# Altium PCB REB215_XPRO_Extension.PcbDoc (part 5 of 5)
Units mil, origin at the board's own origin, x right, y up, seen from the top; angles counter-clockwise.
Board outline 4055.74 x 2606 mil, 6 copper layers (Top Layer LF-signals, Signal Layer 1, Internal Plane 1, Mid-1, Mid-2, Bottom Layer LF-signals), stack 58.434 mil thick; 278 components, 292 nets, 1282 pads, 1177 vias.
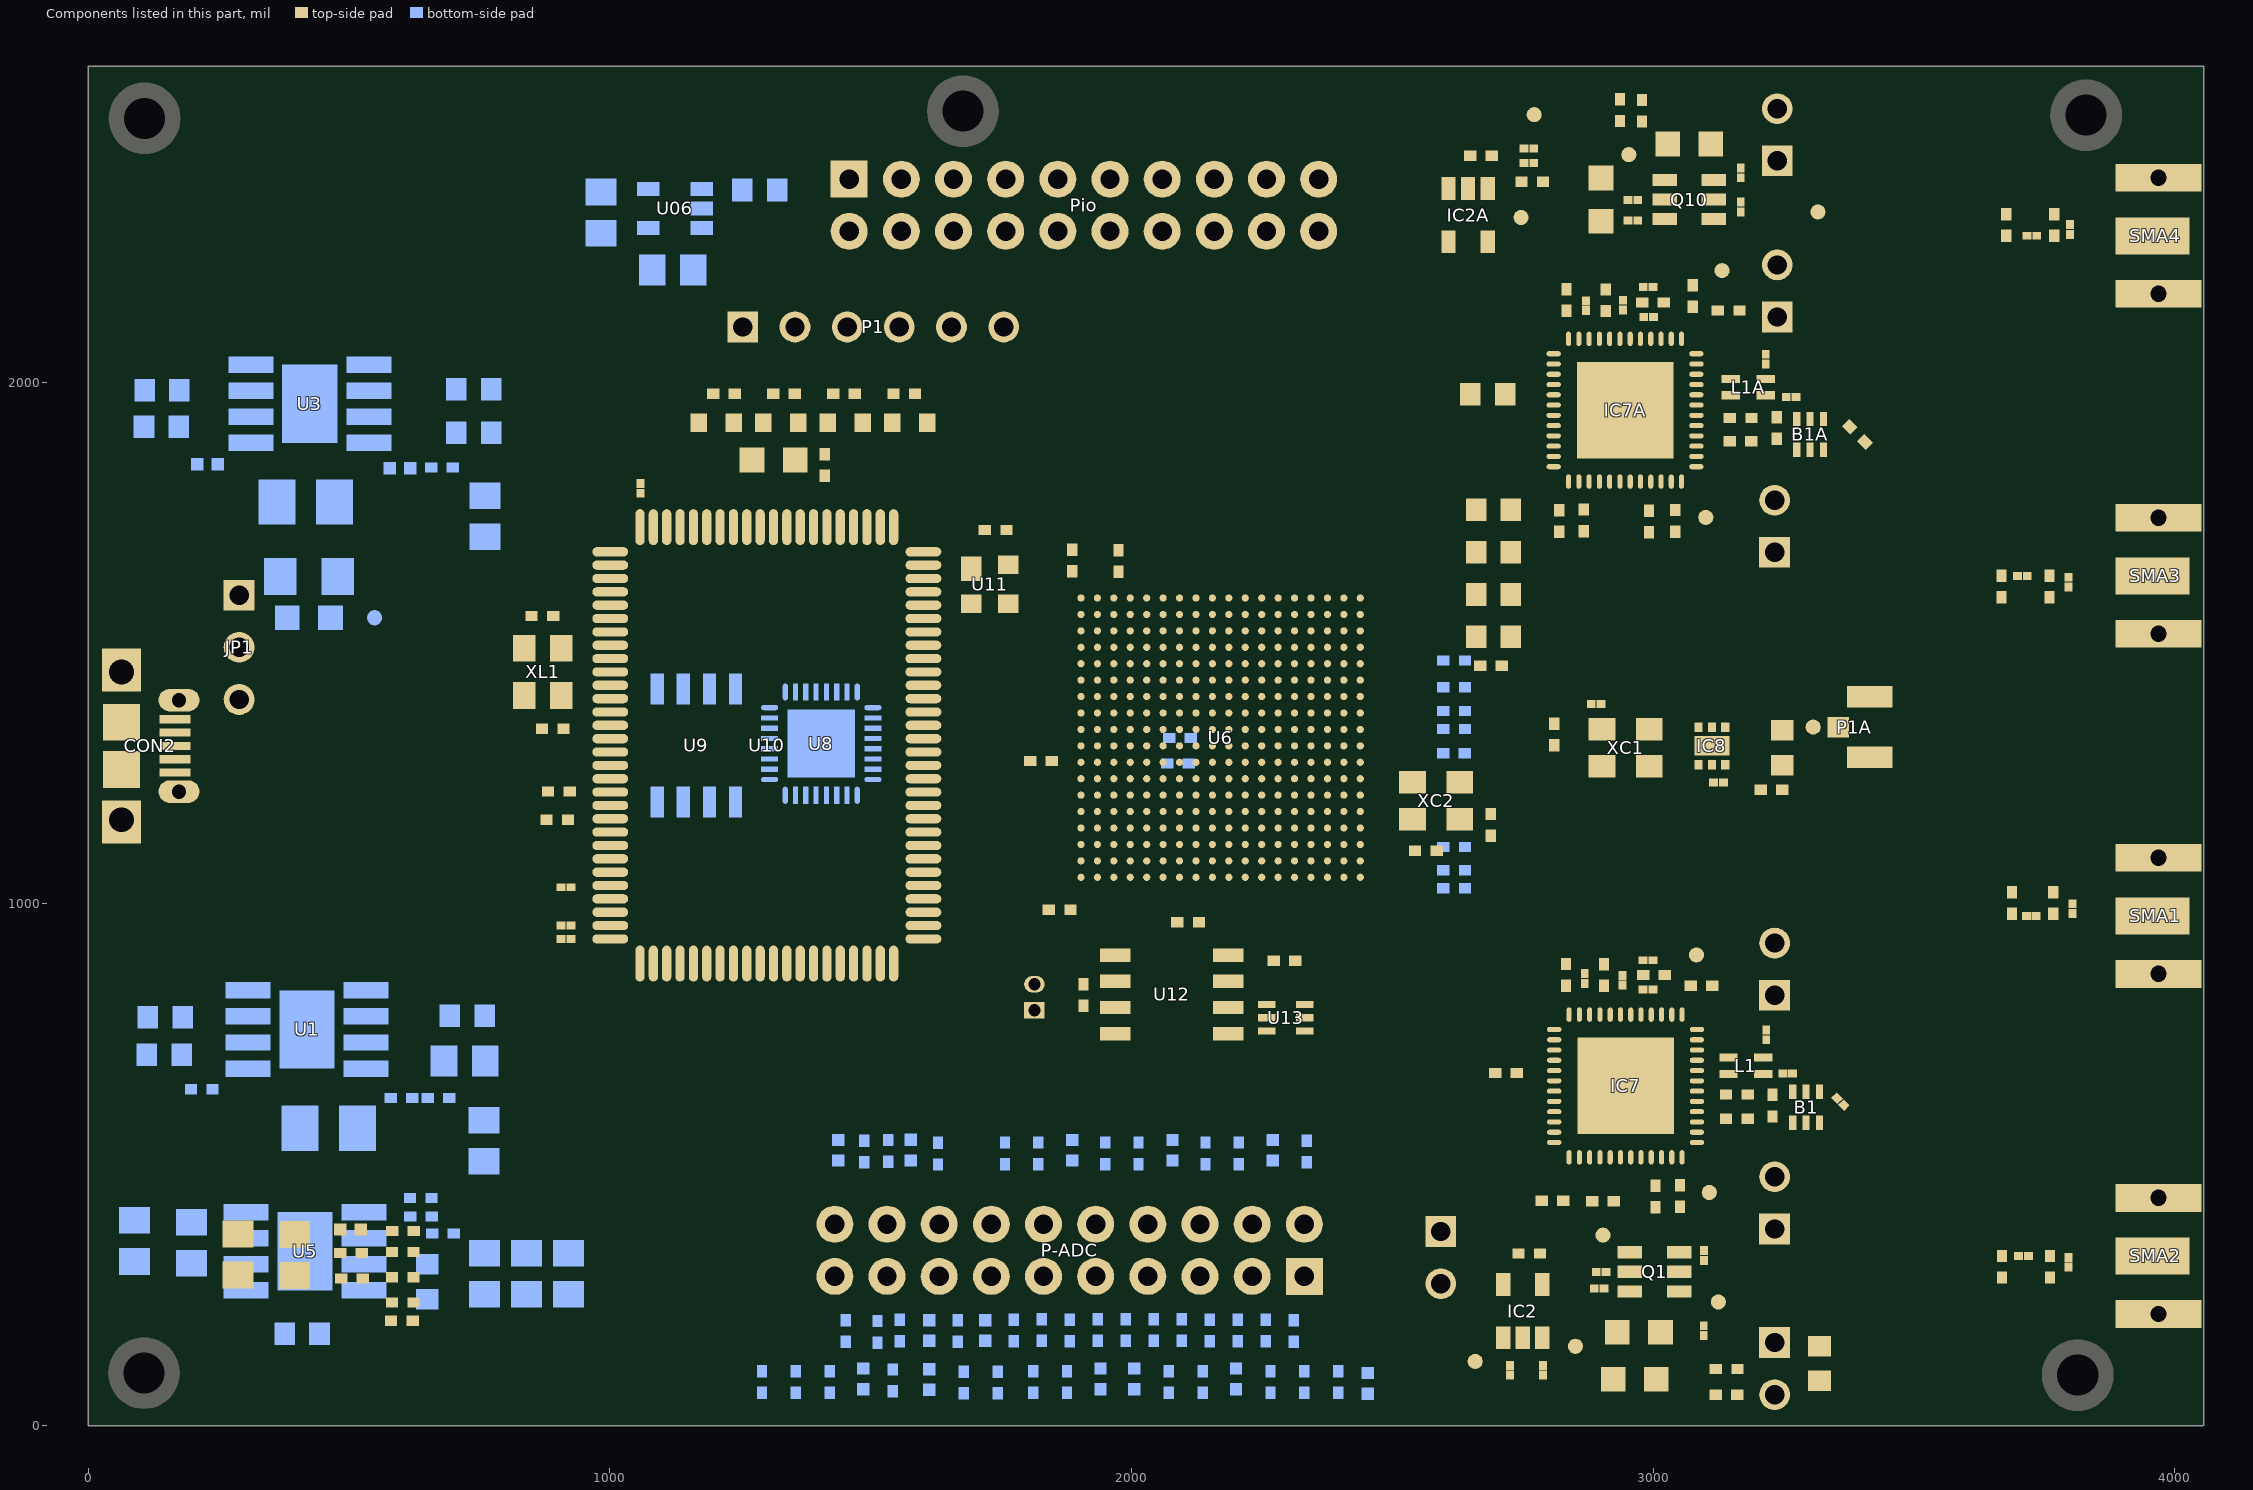
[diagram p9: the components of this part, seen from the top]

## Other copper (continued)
Bottom Layer LF-signals:
  rectangle net VCC: 664,767 714,873.8
  rectangle net NetL4_1: 381,533 438,774
  rectangle net NetC42_2: 259,294 345,374
  rectangle net NetC42_2: 62,299 262,340
  rectangle net NetC42_2: 61,286 230.25,339
  rectangle net VCC: 261,156 343,275
  rectangle net VCC: 261,156 396,197
  rectangle net NetC41_2: 487,153 571.6,275
  rectangle net NetC41_2: 424,153 571.6,197
  rectangle net VCC: 357,1524 415.67,1663.49
  rectangle net VCC: 220,1553 370,1631.91
  rectangle net NetL5_1: 373,1844.87 476,2034
  rectangle net NetL5_1: 326,1728 398,1846.45
  rectangle net NetL5_1: 374,1824 428,1849.35
  rectangle net NetL8_1: 958,2339.15 1097.63,2390
  rectangle net 1V8: 954,2267 1095,2312.05
  rectangle net NetC47_1: 1155,2357 1273,2384
  rectangle net NetC47_1: 1235,2283.65 1274,2389.4
  rectangle net NetC47_1: 1154,2275 1274,2309.03
  rectangle net 2V5: 437,1729.16 708,1814
  rectangle net 2V5: 685,1757 726,1925
  rectangle net 2V5: 643,1755.1 916,1808
  rectangle net NetR23_1: 646,357 674,446.32
  rectangle net 1V0: 688,303.65 1020,381
  rectangle net 1V0: 2586,1255 2610,1298
  rectangle net 1V0: 2586,1253 2689,1272
  rectangle net 1V0: 2586.52,1117 2610,1141.22
  region net 1V0: 2670,1272 2670,1131 2689,1131 2689,1272
  rectangle net 1V0: 2586,1125 2689,1144
  region net 1V0: 2610,1011 2610,1114 2588,1114 2588,1011
  rectangle net 1V8: 951.98,2182.58 1105.31,2244.86
  rectangle net 1V8: 952.94,2184.37 1016.07,2310.76
  rectangle net 1V8: 1047.4,2112.53 1109.41,2242.98
  rectangle net 1V8: 1980.58,1303.59 1999.78,1339.65
  rectangle net VCC: 212,1917.22 355.73,1949.8
  rectangle net VCC: 495,1966 725,2000
  rectangle net VCC: 227,719 349,749
  rectangle net VCC: 489,766 711,800
  rectangle net NetR015_1: 610,618 663,639
  rectangle net 1V8: 2019,1264 2060,1269
  region net 1V8: 2026.24,1270.63 1969.45,1327.42 1962.52,1320.48 2019.3,1263.7
  rectangle net 1V8: 1971.85,1312.49 1981.71,1325.01
  rectangle net 1V8: 2022.2,1266.6 2026.09,1271
  rectangle net 3V3: 680,585.37 708,730
  rectangle net 3V3: 647,669 704,730
  rectangle net 3V3: 704,558 885.97,617.35
  rectangle net 3V3: 480,527 708,597.84
  rectangle net 3V3: 794,558.87 1028,669
  rectangle net 3V3: 1916,1626 1966.97,1647.48
  rectangle net 3V3: 2078,852 2153,934
  rectangle net 3V3: 855,1637 1189,1676
  rectangle net 3V3: 987,625 1028,1670
  rectangle net 3V3: 991,1371 1063,1408.37
  rectangle net 3V3: 1715.91,1790.98 1780.24,1818
  rectangle net GND: 494,2018 581,2099
  rectangle net GND: 87,1889 129,2165
  rectangle net GND: 87,632 137,863.25
  rectangle net GND: 489,819 575.67,905
  rectangle net GND: 741,672 780,918
  rectangle net GND: 729,481 900,530.91
  rectangle net GND: 442,1525.43 625,1665
  rectangle net GND: 2627.59,1335.47 2651.62,1376.6
  rectangle net NetR45_2: 1347,93 1432.06,117
  rectangle net NetR43_2: 1979.26,149 2054,175
  rectangle net NetR44_2: 1872,149 1945,175
  rectangle net NetR44_2: 1867,93 1890,175
  rectangle net CK-AN4-P: 1867,50 1968,74
  rectangle net CK-AN4-P: 1949.78,63 1968.09,79
  rectangle net GND: 361.88,220.32 472.12,451.03
  rectangle net VCC_3V3: 3125,1198.53 3198.6,1289.38
  rectangle net VCC_3V3: 2915.91,1692.91 2973.3,1722
  rectangle net VCC_3V3: 2885.7,1702 2936,1735.33
  rectangle net VCC_TARGET: 2713,2384 2759,2443
  rectangle net VCC_TARGET: 2751,2413 2916,2474
  rectangle net VCC_TARGET: 2748.8,2383 2786.66,2435
  rectangle net VCC_3V3: 3173.07,2424.5 3194,2476
  pour cut-out: 1875,1613.6 1875.45,1614.05 2466.19,1614.05 2466.19,1023.5 1875.64,1023.5 1875.64,1614.05
  pour cut-out: 2538.72,1233.43 2629.28,1233.43 2629.28,1162.57 2538.72,1162.57
  pour cut-out: 1692.3,1568.05 1692.3,1658.61 1763.17,1658.61 1763.17,1568.05
  pour cut-out: 836.01,1489.99 838.47,1487.53 909.34,1487.53 909.34,1387 907.79,1385.46 829.33,1385.46 829.33,1483.31
Internal Plane 1 (plane layer: these items are gaps in the copper):
  pour cut-out: 1875,1613.6 1875.45,1614.05 2466.19,1614.05 2466.19,1023.5 1875.64,1023.5 1875.64,1614.05
  pour cut-out: 2538.72,1233.43 2629.28,1233.43 2629.28,1162.57 2538.72,1162.57
  pour cut-out: 1690.11,1644.99 1690.11,1575.6 1763.43,1575.6 1763.43,1650.4 1693.31,1650.4
  pour cut-out: 836.01,1489.99 838.47,1487.53 909.34,1487.53 909.34,1387 907.79,1385.46 829.33,1385.46 829.33,1483.31

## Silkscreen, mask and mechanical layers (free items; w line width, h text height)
Bottom Overlay:
  circle w10: c1530.35,1419.81 r7.38
Mechanical 1:
  lines w10: 0,0 0,2606 4055.74,2606 4055.74,0.74 4055,0 3957,0 0,0
Mechanical 3:
  lines w10: 4681.58,2179.04 5776.07,2179.04
  text "FABRICATION NOTES" at 4703.23,2213.49 h100
  text "PCB SHEET: FR4 (Er=4.6)" at 4690.22,2075.89 h100
  text "PCB FINISHED THICKNESS: 1.5MM" at 4677.22,1967.09 h100
  text "FINISH: ENIG/PTH" at 4671.22,1858.92 h100
  text "SIGNAL LAYERS: 6(5-Routing,1 GND Plane)" at 4665.1,1754.36 h100
  text "SOLDER MASK: (LPI-BLUE)- TOP and BOTTOM" at 4664,1627.36 h100
  text "SILKSCREEN : WHITE (TOP and BOTTOM)" at 4642,1499.36 h100
  text "E.T : FLYING PROBE" at 4631,1228.36 h100

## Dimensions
0,2606 to 4055.74,2606 on Mechanical 1
4005.75,2604 to 3957,0 on Mechanical 1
